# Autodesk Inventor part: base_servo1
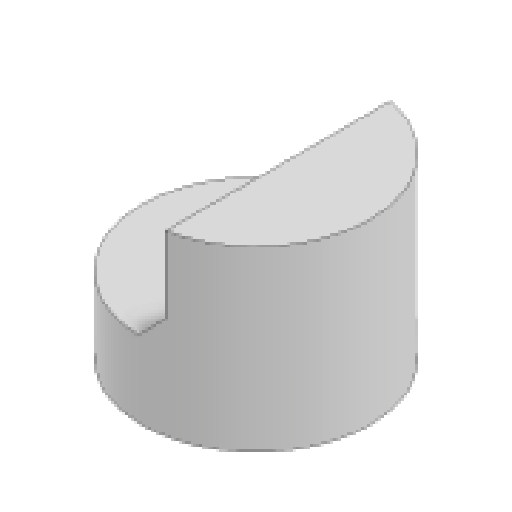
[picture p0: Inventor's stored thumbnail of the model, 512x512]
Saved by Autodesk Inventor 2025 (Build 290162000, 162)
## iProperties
Created: 2025-05
Part Number: base_servo1
Material: Generico
Document SubType Name: Modeling
Designer: R5800u
Density: 1 g/cm^3
Appearance: Default
Author: R5800u
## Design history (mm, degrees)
sketch "Schizzo1"
  geometry: C1 r 45 at (0, 0); 1 further point
  constraints: 1 centre point, 1 coincident
  dimensions: "d0" = 90 diameter of C1
extrude "Estrusione1" new body sketch "Schizzo1" distance "d1" = 48; taper "d2" = 0 deg
sketch "Schizzo2"
  geometry: L1 (8.672, -44.156)-(8.672, 44.156); A1 r 45 centre (0, 0) between (8.672, -44.156) and (8.672, 44.156) reference; A2 r 45 centre (0, 0) between (8.672, -44.156) and (8.672, 44.156) reference; 1 further point
  constraints: 2 end point, 2 point on circle, 1 vertical
extrude "Estrusione2" join sketch "Schizzo2" distance "d3" = 35; taper "d4" = 0 deg
chamfer "Smusso1" distance "d5" = 10; stored, may be unused: second distance "d6" = 2, angle "d7" = 45 deg
sketch "Schizzo3"
  geometry: L1 (12.022, 20.1)-(32.022, 20.1) reference; L2 (32.022, -20)-(12.022, -20) reference; L3 (37.022, 16.1)-(37.022, -16) reference; L4 (8.672, 44.156)-(8.672, -44.156) reference; L5 (8.672, 20.6)-(39.022, 20.6); L6 (39.022, 20.6)-(39.022, -20.5); L7 (39.022, -20.5)-(8.672, -20.5); L8 (8.672, -20.5)-(8.672, 20.6); 2 further points
  constraints: 8 end point, 2 parallel, 1 horizontal, 1 perpendicular, 1 point on line
  dimensions: "d8" = 0.5 distance between parallel lines of L1 L5; "d9" = 0.5 distance between parallel lines of L2 L7; "d10" = 2 distance between parallel lines of L3 L6
  node "Riferimento1"
  node "Riferimento2"
  node "Riferimento3"
node "Piano di lavoro1"
extrude "Estrusione3" cut sketch "Schizzo3" stored distance "d11" = 48; taper "d12" = 0 deg
chamfer "Smusso2" distance "d13" = 2; stored, may be unused: second distance "d14" = 2, angle "d15" = 45 deg
node "Solido1"
